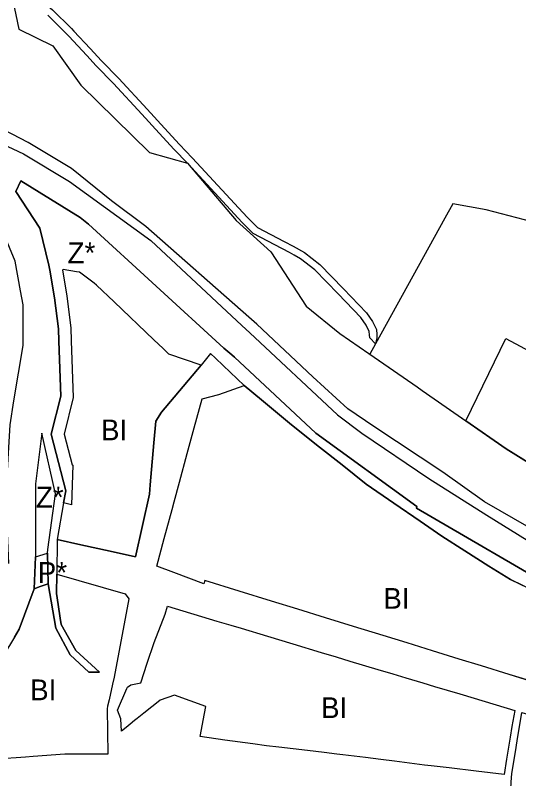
# Model space of a CAD drawing. Extents: x -521621 to -516769, y -1190068 to -1185078.
# Drawn here: x -519976.5 to -519733.8, y -1187252.5 to -1186884.6 of the extents above; entities that cross this region are included whole.
import ezdxf

# ---------------------------------------------------------------- set-up
doc = ezdxf.new("R2010")
doc.units = 0
for name, color, linetype in [('bydleni_s', 7, 'Continuous'), ('rekreace_s', 7, 'Continuous'), ('s_zelen_s', 7, 'Continuous'), ('v_infrastr_s', 7, 'Continuous'), ('voda_s', 7, 'Continuous')]:
    doc.layers.add(name, color=color, linetype=linetype)

msp = doc.modelspace()

# ---------------------------------------------------------------- linework, layer by layer
at = {"layer": 'bydleni_s'}
for p, q in [((-519866.15, -1187062.95), (-519857.72, -1187069.95)), ((-519857.72, -1187069.95), (-519843.32, -1187081.91)), ((-519893.62, -1187095.86), (-519890.25, -1187083.4)), ((-519843.32, -1187081.91), (-519829.78, -1187092.68)), ((-519829.78, -1187092.68), (-519818.92, -1187101.32)), ((-519897.33, -1187109.55), (-519893.62, -1187095.86)), ((-519818.92, -1187101.32), (-519807.26, -1187110.6)), ((-519807.26, -1187110.6), (-519793.94, -1187119.76)), ((-519793.94, -1187119.76), (-519781.37, -1187128.41)), ((-519904.7, -1187136.8), (-519900.9, -1187122.76)), ((-519781.37, -1187128.41), (-519770.85, -1187135.65)), ((-519770.85, -1187135.65), (-519759.77, -1187142.77)), ((-519759.77, -1187142.77), (-519748.26, -1187150.17)), ((-519748.26, -1187150.17), (-519737.74, -1187156.48)), ((-519868.57, -1187162.08), (-519885.09, -1187156.98)), ((-519737.74, -1187156.48), (-519724.84, -1187162.81)), ((-519852.93, -1187166.91), (-519868.57, -1187162.08)), ((-519840.23, -1187170.84), (-519852.93, -1187166.91)), ((-519826.88, -1187174.96), (-519840.23, -1187170.84)), ((-519813.41, -1187179.12), (-519826.88, -1187174.96)), ((-519799.2, -1187183.51), (-519813.41, -1187179.12)), ((-519787.61, -1187187.09), (-519799.2, -1187183.51)), ((-519775.33, -1187190.88), (-519787.61, -1187187.09)), ((-519762.52, -1187194.84), (-519775.33, -1187190.88)), ((-519751.75, -1187198.16), (-519762.52, -1187194.84)), ((-519738.4, -1187202.29), (-519751.75, -1187198.16)), ((-519725.01, -1187206.42), (-519738.4, -1187202.29))]:
    msp.add_line(p, q, dxfattribs=at)
for points in [[(-519947.06, -1187008.16), (-519953.42, -1187007.12), (-519953.77, -1187007.38), (-519951.67, -1187019.74), (-519951.63, -1187020.01), (-519949.73, -1187035.24), (-519949.51, -1187041.51), (-519948.54, -1187068.77), (-519952.98, -1187086.5), (-519949.15, -1187101.22), (-519948.83, -1187101.47)], [(-519911.42, -1187110.83), (-519911.11, -1187107.19), (-519909.69, -1187090.59), (-519908.81, -1187080.26), (-519905.99, -1187075.79), (-519886.92, -1187053.29), (-519902.47, -1187047.91), (-519905.26, -1187045.24), (-519909.74, -1187040.97), (-519928.8, -1187022.75), (-519937.42, -1187014.7), (-519938.49, -1187013.7), (-519945.56, -1187008.41), (-519947.06, -1187008.16)], [(-519890.25, -1187083.4), (-519886.46, -1187069.4), (-519878.33, -1187067.32), (-519866.15, -1187062.95)], [(-519948.83, -1187101.47), (-519949.45, -1187120.49), (-519953.32, -1187119.55), (-519956.35, -1187137.31), (-519944.87, -1187139.82), (-519930.8, -1187142.89), (-519918.52, -1187145.57), (-519911.79, -1187115.46), (-519911.42, -1187110.83)], [(-519900.9, -1187122.76), (-519899.89, -1187119.03), (-519897.33, -1187109.55)], [(-519900.09, -1187153.14), (-519908.29, -1187150.06), (-519904.7, -1187136.8)], [(-519885.09, -1187156.98), (-519885.59, -1187158.59), (-519900.09, -1187153.14)], [(-519956.68, -1187163.34), (-519956.45, -1187154.01), (-519923.46, -1187163.46), (-519921.77, -1187165.78), (-519928.79, -1187203.58)], [(-519976.92, -1187184.39), (-519974.6, -1187180.49), (-519967.44, -1187161.06), (-519964.45, -1187159.95)], [(-519964.45, -1187159.95), (-519960.69, -1187158.56), (-519956.99, -1187180.01), (-519950.05, -1187192.9), (-519941.02, -1187201.23)], [(-519954.91, -1187175.14), (-519955.91, -1187168.49), (-519956.68, -1187163.34)], [(-519904.17, -1187173.22), (-519903.17, -1187169.44), (-519879.29, -1187176.56)], [(-519935.85, -1187201.15), (-519947.34, -1187190.66), (-519954.44, -1187178.24), (-519954.91, -1187175.14)], [(-519909.5, -1187186.88), (-519904.17, -1187173.22)], [(-519879.29, -1187176.56), (-519872.61, -1187178.55), (-519867.61, -1187180.05)], [(-519867.61, -1187180.05), (-519854.89, -1187183.88)], [(-519854.89, -1187183.88), (-519842.64, -1187187.56)], [(-519912.85, -1187196.88), (-519909.5, -1187186.88)], [(-519842.64, -1187187.56), (-519828.96, -1187191.68)], [(-519828.96, -1187191.68), (-519821.84, -1187193.82), (-519815.14, -1187195.82)], [(-519916, -1187206.3), (-519912.85, -1187196.88)], [(-519815.14, -1187195.82), (-519801.64, -1187199.86)], [(-519941.02, -1187201.23), (-519937.35, -1187201.17)], [(-519937.35, -1187201.17), (-519935.85, -1187201.15)], [(-519801.64, -1187199.86), (-519794.47, -1187202)], [(-519928.79, -1187203.58), (-519929.56, -1187206.96), (-519931.27, -1187214.44)], [(-519794.47, -1187202), (-519788.19, -1187203.88)], [(-519788.19, -1187203.88), (-519780.02, -1187206.32), (-519774.31, -1187208.03)], [(-519925.63, -1187223.65), (-519927.29, -1187219.56), (-519922.75, -1187209.05), (-519922.47, -1187208.4), (-519920.76, -1187207.34), (-519916, -1187206.3)], [(-519774.31, -1187208.03), (-519762.2, -1187211.66)], [(-519899.74, -1187212.23), (-519906.7, -1187214.74), (-519907.65, -1187215.49), (-519910.67, -1187217.9), (-519914.5, -1187220.94)], [(-519884.69, -1187217.71), (-519899.74, -1187212.23)], [(-519762.2, -1187211.66), (-519749.95, -1187215.33)], [(-519931.27, -1187214.44), (-519931.99, -1187217.62)], [(-519749.95, -1187215.33), (-519735.73, -1187219.6), (-519737.08, -1187227.37)], [(-519932.26, -1187218.79), (-519931.87, -1187240.63), (-519938.01, -1187240.65), (-519948.74, -1187240.69)], [(-519931.99, -1187217.62), (-519932.26, -1187218.79)], [(-519875.49, -1187233.88), (-519887.3, -1187232.25), (-519885.31, -1187221.1), (-519884.69, -1187217.71)], [(-519914.5, -1187220.94), (-519917.77, -1187223.47), (-519919.01, -1187224.47), (-519921.14, -1187226.2), (-519923.1, -1187227.78), (-519925.28, -1187229.55)], [(-519737.73, -1187260.72), (-519737.35, -1187254.2), (-519737.12, -1187250.04), (-519735.38, -1187239.55), (-519734.51, -1187234.3), (-519732.25, -1187220.68), (-519722.78, -1187223.56), (-519717.7, -1187225.1)], [(-519925.28, -1187229.55), (-519925.63, -1187223.65)], [(-519737.08, -1187227.37), (-519737.98, -1187232.5), (-519739.66, -1187243.04), (-519740.84, -1187250.44), (-519754.27, -1187248.88)], [(-519862.02, -1187235.74), (-519875.49, -1187233.88)], [(-519849.48, -1187237.35), (-519855.44, -1187236.65), (-519862.02, -1187235.74)], [(-519835.66, -1187238.97), (-519849.48, -1187237.35)], [(-519967.83, -1187241.82), (-519971.63, -1187242.1), (-519976.06, -1187242.43)], [(-519948.74, -1187240.69), (-519952.63, -1187240.7), (-519967.83, -1187241.82)], [(-519821.47, -1187240.63), (-519827.52, -1187239.92), (-519835.66, -1187238.97)], [(-519807.68, -1187242.35), (-519818.56, -1187240.97), (-519821.47, -1187240.63)], [(-519976.06, -1187242.43), (-519986.28, -1187243.18)], [(-519800.21, -1187243.3), (-519807.68, -1187242.35)], [(-519793.65, -1187244.13), (-519800.21, -1187243.3)], [(-519779.22, -1187245.96), (-519793.65, -1187244.13)], [(-519767.39, -1187247.36), (-519775.97, -1187246.37), (-519779.22, -1187245.96)], [(-519754.27, -1187248.88), (-519767.39, -1187247.36)]]:
    msp.add_lwpolyline(points, dxfattribs=at)
at = {"layer": 'rekreace_s'}
for points in [[(-519547.18, -1187032.53), (-519550.02, -1187032.47), (-519627.99, -1187001.07), (-519666.78, -1186989.91), (-519712.58, -1186987.97), (-519749.55, -1186978.37), (-519765.51, -1186975.38), (-519769.39, -1186982.4)], [(-519769.39, -1186982.4), (-519802.87, -1187042.97)], [(-519802.87, -1187042.97), (-519805.59, -1187047.89)], [(-519759.25, -1187080.06), (-519740.02, -1187040.35), (-519721.62, -1187050.23), (-519690.13, -1187066.85), (-519671.19, -1187076.71), (-519695.81, -1187120.87)], [(-519805.59, -1187047.89), (-519782.78, -1187063.7)], [(-519782.78, -1187063.7), (-519780.3, -1187065.42), (-519759.25, -1187080.06)]]:
    msp.add_lwpolyline(points, dxfattribs=at)
msp.add_lwpolyline([(-519721.62, -1187050.23), (-519690.13, -1187066.85), (-519671.19, -1187076.71), (-519695.81, -1187120.87), (-519739.82, -1187093.57), (-519759.25, -1187080.06), (-519740.02, -1187040.35)], close=True, dxfattribs=at)
at = {"layer": 's_zelen_s'}
for points in [[(-519976.25, -1186969.59), (-519973.89, -1186964.34), (-519945.18, -1186982.09), (-519941.17, -1186985.33), (-519876.04, -1187044.95), (-519872.07, -1187048.29), (-519870.88, -1187049.41), (-519831.64, -1187086.03), (-519782.87, -1187121.37), (-519783.03, -1187122.14), (-519711.27, -1187163.96), (-519691.98, -1187171.68), (-519636.11, -1187188.04), (-519566.51, -1187196.52), (-519488.58, -1187203.01), (-519374.38, -1187202.7), (-519363.08, -1187202.74), (-519276.38, -1187203.01), (-519187.84, -1187203.66), (-519142.54, -1187204.74), (-519110.53, -1187206.31), (-519088.84, -1187207.37)], [(-519964.74, -1186987.19), (-519976.25, -1186969.59)], [(-519959.86, -1187007.38), (-519960.28, -1187004.95), (-519964.74, -1186987.19)], [(-519955.51, -1187041.72), (-519955.72, -1187035.72), (-519957.58, -1187020.75), (-519959.86, -1187007.38)], [(-519886.92, -1187053.29), (-519902.47, -1187047.91), (-519905.26, -1187045.24), (-519909.74, -1187040.97), (-519928.8, -1187022.75), (-519937.42, -1187014.7), (-519938.49, -1187013.7), (-519945.56, -1187008.41), (-519947.06, -1187008.16), (-519953.42, -1187007.12), (-519953.77, -1187007.38)], [(-519953.77, -1187007.38), (-519951.67, -1187019.74)], [(-519951.67, -1187019.74), (-519951.63, -1187020.01), (-519949.73, -1187035.24), (-519949.51, -1187041.51), (-519948.54, -1187068.77), (-519952.98, -1187086.5), (-519949.15, -1187101.22), (-519948.83, -1187101.47)], [(-519953.32, -1187119.55), (-519952.07, -1187113.8), (-519959.17, -1187086.53), (-519954.57, -1187068.14), (-519955.51, -1187041.72)], [(-519882.31, -1187047.61), (-519886.92, -1187053.29)], [(-519724.84, -1187162.81), (-519737.74, -1187156.48), (-519748.26, -1187150.17), (-519759.77, -1187142.77), (-519770.85, -1187135.65), (-519781.37, -1187128.41), (-519793.94, -1187119.76), (-519807.26, -1187110.6), (-519818.92, -1187101.32), (-519829.78, -1187092.68), (-519843.32, -1187081.91), (-519857.72, -1187069.95), (-519866.15, -1187062.95), (-519876.21, -1187053.4), (-519880.01, -1187049.8), (-519882.31, -1187047.61)], [(-519966.72, -1187139.73), (-519966.7, -1187145.62), (-519961, -1187143.82), (-519960.76, -1187142.08), (-519957.14, -1187115.27), (-519963.72, -1187086.02), (-519966.79, -1187110.48), (-519966.72, -1187139.73)], [(-519948.83, -1187101.47), (-519949.45, -1187120.49), (-519953.32, -1187119.55)]]:
    msp.add_lwpolyline(points, dxfattribs=at)
at = {"layer": 'v_infrastr_s'}
msp.add_line((-519914.5, -1187220.94), (-519914.5, -1187220.94), dxfattribs=at)
for points in [[(-519976.16, -1186871.44), (-519970.65, -1186873.19), (-519964.56, -1186876.79), (-519958.52, -1186882), (-519949.44, -1186890.96)], [(-519978.4, -1186874.16), (-519974.77, -1186891.32)], [(-519942.03, -1186903.96), (-519950.74, -1186894.61), (-519960.89, -1186884.57)], [(-519974.77, -1186891.32), (-519958.42, -1186899.36)], [(-519949.44, -1186890.96), (-519948.22, -1186892.17), (-519940.37, -1186900.61)], [(-519958.42, -1186899.36), (-519944.93, -1186918.3)], [(-519940.37, -1186900.61), (-519934.93, -1186906.46), (-519926.58, -1186915.07), (-519912.93, -1186929.85), (-519904.54, -1186939), (-519897.38, -1186946.83), (-519891.29, -1186953.22)], [(-519893.55, -1186955.92), (-519899.94, -1186949.22), (-519907.13, -1186941.37), (-519915.51, -1186932.22), (-519929.13, -1186917.48), (-519937.47, -1186908.87), (-519942.03, -1186903.96)], [(-519944.93, -1186918.3), (-519911.85, -1186950.73)], [(-519860.1, -1187033.53), (-519863.94, -1187030.15), (-519913.58, -1186986.44), (-519930.08, -1186973.99), (-519949.41, -1186958.4), (-519970.36, -1186945.95), (-519989.93, -1186935.79), (-520007.61, -1186926.56)], [(-519911.85, -1186950.73), (-519893.55, -1186955.92)], [(-519891.29, -1186953.22), (-519891, -1186953.52), (-519864.66, -1186981.95), (-519859.73, -1186986.88), (-519846.93, -1186993.63)], [(-519893.55, -1186955.92), (-519870.07, -1186983.56)], [(-519842.06, -1187000.22), (-519844.26, -1186998.99), (-519861.83, -1186989.73), (-519867.18, -1186984.38), (-519893.55, -1186955.92)], [(-519870.07, -1186983.56), (-519853.34, -1186998.61)], [(-519846.93, -1186993.63), (-519842.59, -1186995.92), (-519837.13, -1186998.96), (-519829.69, -1187004.72), (-519818.32, -1187016.38), (-519807.12, -1187028.03), (-519804.33, -1187032.14), (-519802.42, -1187036.04), (-519802.18, -1187038.37), (-519802.14, -1187040.11), (-519802.87, -1187042.97), (-519805.64, -1187040.01), (-519805.68, -1187038.6), (-519805.84, -1187037.02), (-519807.36, -1187033.9), (-519809.85, -1187030.24), (-519820.83, -1187018.81), (-519832.03, -1187007.33), (-519839.07, -1187001.89), (-519842.06, -1187000.22)], [(-519853.34, -1186998.61), (-519836.34, -1187024.81)], [(-519836.34, -1187024.81), (-519820, -1187037.91)], [(-519833.1, -1187058.78), (-519860.1, -1187033.53)], [(-519820, -1187037.91), (-519782.78, -1187063.7)], [(-519725.01, -1187206.42), (-519738.4, -1187202.29), (-519751.75, -1187198.16), (-519762.52, -1187194.84), (-519775.33, -1187190.88), (-519787.61, -1187187.09), (-519799.2, -1187183.51), (-519813.41, -1187179.12), (-519826.88, -1187174.96), (-519840.23, -1187170.84), (-519852.93, -1187166.91), (-519868.57, -1187162.08), (-519885.09, -1187156.98), (-519885.59, -1187158.59), (-519900.09, -1187153.14), (-519908.29, -1187150.06), (-519904.7, -1187136.8), (-519900.9, -1187122.76), (-519899.89, -1187119.03), (-519897.33, -1187109.55), (-519893.62, -1187095.86), (-519890.25, -1187083.4), (-519886.46, -1187069.4), (-519878.33, -1187067.32), (-519866.15, -1187062.95), (-519876.21, -1187053.4), (-519880.01, -1187049.8), (-519882.31, -1187047.61), (-519886.92, -1187053.29), (-519905.99, -1187075.79), (-519908.81, -1187080.26)], [(-519816.25, -1187074.21), (-519833.1, -1187058.78)], [(-519782.78, -1187063.7), (-519780.3, -1187065.42)], [(-519780.3, -1187065.42), (-519739.82, -1187093.57)], [(-519803.59, -1187082.78), (-519816.25, -1187074.21)], [(-519908.81, -1187080.26), (-519909.69, -1187090.59), (-519911.11, -1187107.19), (-519911.42, -1187110.83), (-519911.79, -1187115.46), (-519918.52, -1187145.57)], [(-519770.3, -1187104.81), (-519803.59, -1187082.78)], [(-519739.82, -1187093.57), (-519687.54, -1187126)], [(-519750.27, -1187119.06), (-519770.3, -1187104.81)], [(-519728.74, -1187131.52), (-519750.27, -1187119.06)], [(-519918.52, -1187145.57), (-519930.8, -1187142.89), (-519944.87, -1187139.82), (-519956.35, -1187137.31), (-519956.45, -1187154.01), (-519923.46, -1187163.46), (-519921.77, -1187165.78), (-519928.79, -1187203.58), (-519929.56, -1187206.96), (-519931.27, -1187214.44), (-519931.99, -1187217.62), (-519932.26, -1187218.79), (-519931.87, -1187240.63), (-519938.01, -1187240.65), (-519948.74, -1187240.69), (-519952.63, -1187240.7), (-519967.83, -1187241.82), (-519971.63, -1187242.1), (-519976.06, -1187242.43), (-519986.28, -1187243.18), (-519985.96, -1187247.03), (-520001.09, -1187248.72), (-520020.12, -1187250.41)], [(-519904.17, -1187173.22), (-519903.17, -1187169.44)], [(-519903.17, -1187169.44), (-519879.29, -1187176.56)], [(-519909.5, -1187186.88), (-519904.17, -1187173.22)], [(-519879.29, -1187176.56), (-519872.61, -1187178.55)], [(-519872.61, -1187178.55), (-519867.61, -1187180.05)], [(-519867.61, -1187180.05), (-519854.89, -1187183.88)], [(-519854.89, -1187183.88), (-519842.64, -1187187.56)], [(-519912.85, -1187196.88), (-519909.5, -1187186.88)], [(-519842.64, -1187187.56), (-519828.96, -1187191.68)], [(-519828.96, -1187191.68), (-519821.84, -1187193.82)], [(-519821.84, -1187193.82), (-519815.14, -1187195.82)], [(-519916, -1187206.3), (-519912.85, -1187196.88)], [(-519815.14, -1187195.82), (-519801.64, -1187199.86)], [(-519801.64, -1187199.86), (-519794.47, -1187202)], [(-519794.47, -1187202), (-519788.19, -1187203.88)], [(-519788.19, -1187203.88), (-519780.02, -1187206.32)], [(-519922.75, -1187209.05), (-519922.47, -1187208.4)], [(-519922.47, -1187208.4), (-519920.76, -1187207.34)], [(-519920.76, -1187207.34), (-519916, -1187206.3)], [(-519780.02, -1187206.32), (-519774.31, -1187208.03)], [(-519774.31, -1187208.03), (-519762.2, -1187211.66)], [(-519927.29, -1187219.56), (-519922.75, -1187209.05)], [(-519899.74, -1187212.23), (-519906.7, -1187214.74)], [(-519884.69, -1187217.71), (-519899.74, -1187212.23)], [(-519762.2, -1187211.66), (-519749.95, -1187215.33)], [(-519907.65, -1187215.49), (-519910.67, -1187217.9)], [(-519906.7, -1187214.74), (-519907.65, -1187215.49)], [(-519749.95, -1187215.33), (-519735.73, -1187219.6)], [(-519925.63, -1187223.65), (-519927.29, -1187219.56)], [(-519910.67, -1187217.9), (-519914.5, -1187220.94)], [(-519885.31, -1187221.1), (-519884.69, -1187217.71)], [(-519735.73, -1187219.6), (-519737.08, -1187227.37)], [(-519917.77, -1187223.47), (-519919.01, -1187224.47)], [(-519914.5, -1187220.94), (-519917.77, -1187223.47)], [(-519887.3, -1187232.25), (-519885.31, -1187221.1)], [(-519737.35, -1187254.2), (-519737.12, -1187250.04), (-519735.38, -1187239.55), (-519734.51, -1187234.3), (-519732.25, -1187220.68), (-519722.78, -1187223.56), (-519717.7, -1187225.1), (-519705.52, -1187228.79), (-519699.07, -1187230.75), (-519688.73, -1187233.89), (-519674.48, -1187238.21), (-519667.79, -1187240.25), (-519663.98, -1187241.4), (-519648.55, -1187246.09), (-519645.83, -1187246.91), (-519646.91, -1187253.08)], [(-519925.28, -1187229.55), (-519925.63, -1187223.65)], [(-519921.14, -1187226.2), (-519923.1, -1187227.78)], [(-519919.01, -1187224.47), (-519921.14, -1187226.2)], [(-519923.1, -1187227.78), (-519925.28, -1187229.55)], [(-519737.08, -1187227.37), (-519737.98, -1187232.5)], [(-519875.49, -1187233.88), (-519887.3, -1187232.25)], [(-519862.02, -1187235.74), (-519875.49, -1187233.88)], [(-519737.98, -1187232.5), (-519739.66, -1187243.04)], [(-519855.44, -1187236.65), (-519862.02, -1187235.74)], [(-519849.48, -1187237.35), (-519855.44, -1187236.65)], [(-519835.66, -1187238.97), (-519849.48, -1187237.35)], [(-519827.52, -1187239.92), (-519835.66, -1187238.97)], [(-519821.47, -1187240.63), (-519827.52, -1187239.92)], [(-519818.56, -1187240.97), (-519821.47, -1187240.63)], [(-519807.68, -1187242.35), (-519818.56, -1187240.97)], [(-519800.21, -1187243.3), (-519807.68, -1187242.35)], [(-519793.65, -1187244.13), (-519800.21, -1187243.3)], [(-519779.22, -1187245.96), (-519793.65, -1187244.13)], [(-519739.66, -1187243.04), (-519740.84, -1187250.44)], [(-519775.97, -1187246.37), (-519779.22, -1187245.96)], [(-519767.39, -1187247.36), (-519775.97, -1187246.37)], [(-519754.27, -1187248.88), (-519767.39, -1187247.36)], [(-519740.84, -1187250.44), (-519754.27, -1187248.88)]]:
    msp.add_lwpolyline(points, dxfattribs=at)
msp.add_lwpolyline([(-519967.44, -1187161.06), (-519966.7, -1187145.62), (-519961, -1187143.82), (-519960.69, -1187158.56), (-519964.45, -1187159.95)], close=True, dxfattribs=at)
at = {"layer": 'voda_s'}
for points in [[(-520317.35, -1186794.57), (-520183.23, -1186854.16), (-520082.33, -1186900.21), (-519990.94, -1186942.77), (-519990.94, -1186942.77), (-519972.47, -1186951.37), (-519950.32, -1186964.73), (-519911.12, -1186993.2), (-519867.23, -1187034.17), (-519863.47, -1187037.69), (-519821.12, -1187077.22), (-519809.35, -1187086.01), (-519777.18, -1187107.81), (-519749.23, -1187125.56), (-519729.72, -1187137.52), (-519713.37, -1187145.6), (-519684.37, -1187157.2), (-519662.4, -1187164.59), (-519633.74, -1187171.44), (-519582.24, -1187178.82), (-519519.49, -1187187.61)], [(-519488.58, -1187203.01), (-519566.51, -1187196.52), (-519636.11, -1187188.04), (-519691.98, -1187171.68), (-519711.27, -1187163.96), (-519783.03, -1187122.14), (-519782.87, -1187121.37), (-519831.64, -1187086.03), (-519870.88, -1187049.41), (-519872.07, -1187048.29), (-519876.04, -1187044.95), (-519941.17, -1186985.33), (-519945.18, -1186982.09), (-519973.89, -1186964.34), (-519976.25, -1186969.59)], [(-519973.95, -1187017.39), (-519976.57, -1187003.02), (-519984.11, -1186985.31), (-519994.79, -1186969.47)], [(-519976.25, -1186969.59), (-519964.74, -1186987.19), (-519960.28, -1187004.95), (-519959.86, -1187007.38), (-519957.58, -1187020.75)], [(-519979.66, -1187148.75), (-519980.11, -1187137.79), (-519980.19, -1187134.19), (-519980.67, -1187112.17), (-519978.95, -1187081.91), (-519977.27, -1187070.47), (-519972.76, -1187043.74), (-519972.72, -1187024.12), (-519973.95, -1187017.39)], [(-519957.58, -1187020.75), (-519955.72, -1187035.72)], [(-519955.72, -1187035.72), (-519955.51, -1187041.72), (-519954.57, -1187068.14), (-519959.17, -1187086.53), (-519952.07, -1187113.8), (-519953.32, -1187119.55), (-519956.35, -1187137.31)], [(-519963.72, -1187086.02), (-519966.79, -1187110.48), (-519966.72, -1187139.73), (-519966.7, -1187145.62), (-519967.44, -1187161.06), (-519974.6, -1187180.49), (-519976.92, -1187184.39), (-519982.08, -1187192.81), (-519989.47, -1187204.85), (-520008.16, -1187231.72), (-520020.12, -1187250.41)], [(-519956.45, -1187154.01), (-519956.68, -1187163.34), (-519955.91, -1187168.49), (-519954.91, -1187175.14), (-519954.44, -1187178.24), (-519947.34, -1187190.66), (-519935.85, -1187201.15), (-519937.35, -1187201.17), (-519941.02, -1187201.23), (-519950.05, -1187192.9), (-519956.99, -1187180.01), (-519960.69, -1187158.56), (-519961, -1187143.82), (-519960.76, -1187142.08), (-519957.14, -1187115.27), (-519963.72, -1187086.02)], [(-519956.35, -1187137.31), (-519956.45, -1187154.01)]]:
    msp.add_lwpolyline(points, dxfattribs=at)

# ---------------------------------------------------------------- texts
at = {"layer": 'bydleni_s'}
for p in [(-519935.19, -1187089.43), (-519799.07, -1187170.62), (-519969.35, -1187214.71), (-519829.09, -1187223.31)]:
    msp.add_text('BI', height=10, dxfattribs=at).set_placement(p)
at = {"layer": 's_zelen_s'}
for p in [(-519951.29, -1187004.08), (-519966.55, -1187121.85)]:
    msp.add_text('Z*', height=10, dxfattribs=at).set_placement(p)
at = {"layer": 'v_infrastr_s'}
msp.add_text('P*', height=10, dxfattribs=at).set_placement((-519965.67, -1187158.14))

doc.saveas('drawing.dxf')
